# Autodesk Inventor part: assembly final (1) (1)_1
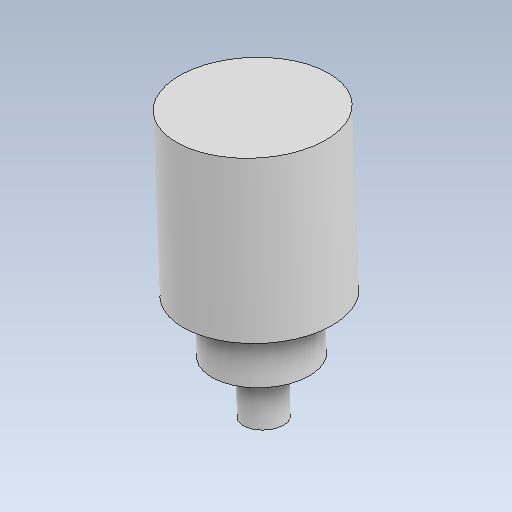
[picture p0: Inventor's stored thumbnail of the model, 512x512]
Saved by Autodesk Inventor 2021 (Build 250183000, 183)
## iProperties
Created: 2021-07
Part Number: assembly final (1) (1)_1
Material: Generic
Document SubType Name: Modeling
Designer: TARUN
Density: 1 g/cm^3
Appearance: Default
Author: TARUN
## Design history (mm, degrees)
feature "Base1"
body "Solid1"
